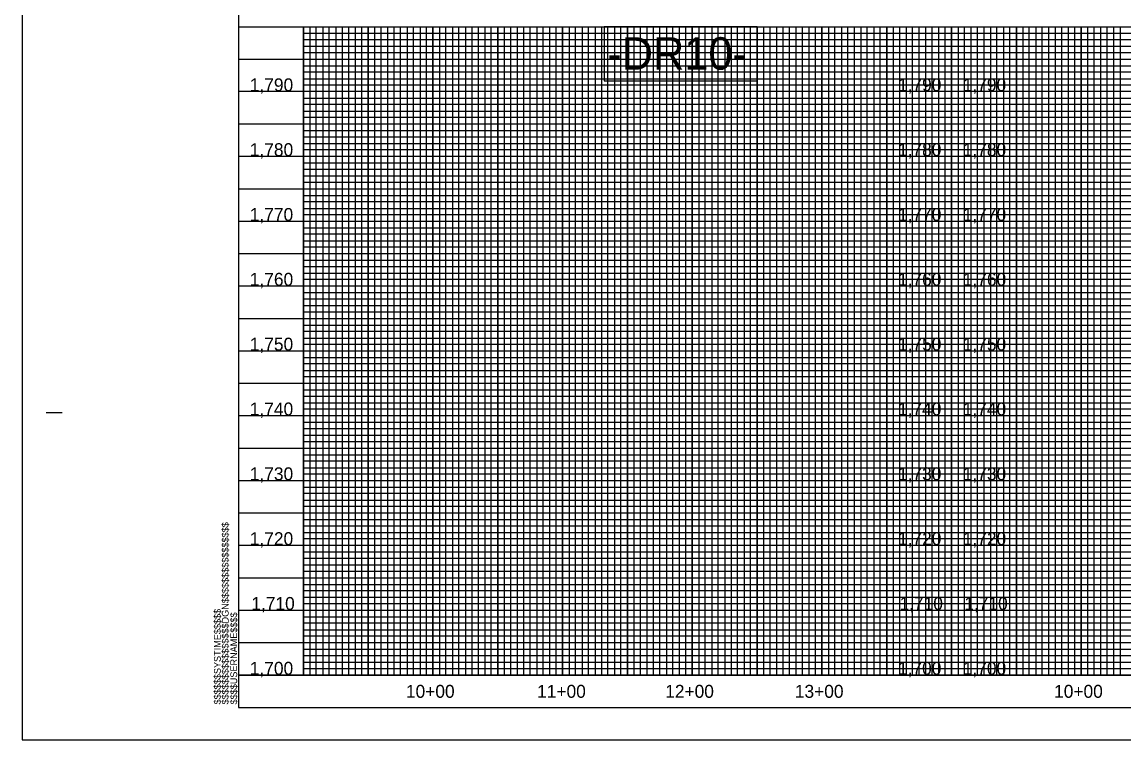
# Model space of a CAD drawing. Extents: x 505602 to 507286, y 483109 to 484209.
# Drawn here: x 505602 to 506452, y 483109 to 483662 of the extents above; entities that cross this region are included whole.
import ezdxf

# ---------------------------------------------------------------- set-up
doc = ezdxf.new("R2010")
doc.units = 0
for name, color, linetype in [('Exist Vertical Profile Vertical Axis Label', 7, 'Continuous'), ('Old_Level_1', 7, 'Continuous'), ('Prop Grid Mask', 7, 'Continuous'), ('Sheet Layout Profile Border Port 2', 7, 'Continuous'), ('Sheet Plot Border Outside CELL', 7, 'Continuous'), ('Sheet Profile CELL', 7, 'Continuous'), ('Sheet Profile Grid Major CELL', 7, 'Continuous'), ('Sheet Profile Grid Middle CELL', 7, 'Continuous'), ('Sheet Profile Grid Minor CELL', 7, 'Continuous')]:
    doc.layers.add(name, color=color, linetype=linetype)

msp = doc.modelspace()

# ---------------------------------------------------------------- linework, layer by layer
at = {"layer": 'Prop Grid Mask'}
msp.add_lwpolyline([(506169.08, 483658.71), (506051.19, 483658.71), (506051.19, 483617), (506169.08, 483617)], close=True, dxfattribs=at)
at = {"layer": 'Sheet Layout Profile Border Port 2'}
for points in [[(505819.08, 483658.71), (506319.08, 483658.71), (506319.08, 483158.71), (505819.08, 483158.71)], [(506319.08, 483658.71), (506719.08, 483658.71), (506719.08, 483158.71), (506319.08, 483158.71)]]:
    msp.add_lwpolyline(points, close=True, dxfattribs=at)
at = {"layer": 'Sheet Plot Border Outside CELL'}
msp.add_lwpolyline([(505602.08, 483108.71), (507286.08, 483108.71), (507286.08, 484208.71), (505602.08, 484208.71)], close=True, dxfattribs=at)
at = {"layer": 'Sheet Profile CELL'}
for p, q in [((505769.08, 483658.71), (507269.08, 483658.71)), ((506319.08, 483158.71), (506319.08, 483658.71)), ((505620.58, 483361.21), (505633.08, 483361.21)), ((507269.08, 483158.71), (505769.08, 483158.71)), ((505769.08, 483133.71), (507269.08, 483133.71)), ((505769.08, 483133.71), (505769.08, 483133.71)), ((505769.08, 483133.71), (505769.08, 483133.71)), ((505769.08, 483133.71), (505769.08, 483133.71)), ((505769.08, 483133.71), (505769.08, 483133.71)), ((505769.08, 483133.71), (505769.08, 483133.71)), ((505769.08, 483133.71), (505769.08, 483133.71)), ((505769.08, 483133.71), (505769.08, 483133.71))]:
    msp.add_line(p, q, dxfattribs=at)
msp.add_lwpolyline([(507269.08, 484183.71), (505769.08, 484183.71), (505769.08, 483133.71), (507269.08, 483133.71)], close=True, dxfattribs=at)
msp.add_lwpolyline([(505806.58, 483133.71), (505806.58, 483133.71)], dxfattribs=at)
at = {"layer": 'Sheet Profile Grid Major CELL'}
for p, q in [((506269.08, 483658.71), (506319.08, 483658.71)), ((506369.08, 483658.71), (506419.08, 483658.71))]:
    msp.add_line(p, q, dxfattribs=at)
for points in [[(505769.08, 483658.71), (505769.08, 483158.71), (505819.08, 483158.71), (505819.08, 483658.71), (505869.08, 483658.71), (505869.08, 483158.71), (505919.08, 483158.71), (505919.08, 483658.71), (505969.08, 483658.71), (505969.08, 483158.71), (506019.08, 483158.71), (506019.08, 483658.71), (506069.08, 483658.71), (506069.08, 483158.71), (506119.08, 483158.71), (506119.08, 483658.71), (506169.08, 483658.71), (506169.08, 483158.71), (506219.08, 483158.71), (506219.08, 483658.71), (506269.08, 483658.71), (506269.08, 483158.71), (506319.08, 483158.71), (506319.08, 483658.71), (506369.08, 483658.71), (506369.08, 483158.71), (506419.08, 483158.71), (506419.08, 483658.71), (506469.08, 483658.71)], [(505819.08, 483658.71), (505819.08, 483158.71), (505869.08, 483158.71), (505869.08, 483658.71), (505919.08, 483658.71), (505919.08, 483158.71), (505969.08, 483158.71), (505969.08, 483658.71), (506019.08, 483658.71), (506019.08, 483158.71), (506069.08, 483158.71), (506069.08, 483658.71), (506119.08, 483658.71), (506119.08, 483158.71), (506169.08, 483158.71), (506169.08, 483658.71), (506219.08, 483658.71), (506219.08, 483158.71), (506269.08, 483158.71), (506269.08, 483658.71), (506319.08, 483658.71), (506319.08, 483158.71), (506369.08, 483158.71), (506369.08, 483658.71), (506419.08, 483658.71), (506419.08, 483158.71), (506469.08, 483158.71)], [(507269.08, 483608.71), (505769.08, 483608.71)], [(507269.08, 483558.71), (505769.08, 483558.71), (505769.08, 483508.71), (507269.08, 483508.71)], [(507269.08, 483458.71), (505769.08, 483458.71), (505769.08, 483408.71), (507269.08, 483408.71)], [(507269.08, 483358.71), (505769.08, 483358.71), (505769.08, 483308.71), (507269.08, 483308.71)], [(507269.08, 483258.71), (505769.08, 483258.71), (505769.08, 483258.71), (505769.08, 483208.71), (507269.08, 483208.71)], [(507269.08, 483158.71), (505769.08, 483158.71)]]:
    msp.add_lwpolyline(points, dxfattribs=at)
at = {"layer": 'Sheet Profile Grid Middle CELL'}
for points in [[(505794.08, 483658.71), (505844.08, 483658.71), (505844.08, 483158.71), (505894.08, 483158.71), (505894.08, 483658.71), (505944.08, 483658.71), (505944.08, 483158.71), (505994.08, 483158.71), (505994.08, 483658.71), (506044.08, 483658.71), (506044.08, 483158.71), (506094.08, 483158.71), (506094.08, 483658.71), (506144.08, 483658.71), (506144.08, 483158.71), (506194.08, 483158.71), (506194.08, 483658.71), (506244.08, 483658.71), (506244.08, 483158.71), (506294.08, 483158.71), (506294.08, 483658.71), (506344.08, 483658.71), (506344.08, 483158.71), (506394.08, 483158.71), (506394.08, 483158.71), (506394.08, 483658.71), (506444.08, 483658.71), (506444.08, 483158.71), (506494.08, 483158.71)], [(505769.08, 483633.71), (507269.08, 483633.71)], [(507269.08, 483583.71), (505769.08, 483583.71), (505769.08, 483533.71), (507269.08, 483533.71)], [(507269.08, 483483.71), (505769.08, 483483.71), (505769.08, 483433.71), (507269.08, 483433.71)], [(507269.08, 483383.71), (505769.08, 483383.71), (505769.08, 483333.71), (507269.08, 483333.71)], [(507269.08, 483283.71), (505769.08, 483283.71), (505769.08, 483233.71), (507269.08, 483233.71)], [(507269.08, 483183.71), (505769.08, 483183.71)]]:
    msp.add_lwpolyline(points, dxfattribs=at)
at = {"layer": 'Sheet Profile Grid Minor CELL'}
for p, q in [((505819.08, 483653.71), (507219.08, 483653.71)), ((507219.08, 483648.71), (505819.08, 483648.71)), ((505819.08, 483643.71), (507219.08, 483643.71)), ((507219.08, 483638.71), (505819.08, 483638.71)), ((505819.08, 483628.71), (507219.08, 483628.71)), ((507219.08, 483623.71), (505819.08, 483623.71)), ((505819.08, 483618.71), (507219.08, 483618.71)), ((507219.08, 483613.71), (505819.08, 483613.71)), ((505819.08, 483603.71), (507219.08, 483603.71)), ((507219.08, 483598.71), (505819.08, 483598.71)), ((505819.08, 483593.71), (507219.08, 483593.71)), ((507219.08, 483588.71), (505819.08, 483588.71)), ((505819.08, 483578.71), (507219.08, 483578.71)), ((507219.08, 483573.71), (505819.08, 483573.71)), ((505819.08, 483568.71), (507219.08, 483568.71)), ((507219.08, 483563.71), (505819.08, 483563.71)), ((505819.08, 483553.71), (507219.08, 483553.71)), ((507219.08, 483548.71), (505819.08, 483548.71)), ((505819.08, 483543.71), (507219.08, 483543.71)), ((507219.08, 483538.71), (505819.08, 483538.71)), ((505819.08, 483528.71), (507219.08, 483528.71)), ((507219.08, 483523.71), (505819.08, 483523.71)), ((505819.08, 483518.71), (507219.08, 483518.71)), ((507219.08, 483513.71), (505819.08, 483513.71)), ((505819.08, 483503.71), (507219.08, 483503.71)), ((507219.08, 483498.71), (505819.08, 483498.71)), ((505819.08, 483493.71), (507219.08, 483493.71)), ((507219.08, 483488.71), (505819.08, 483488.71)), ((505819.08, 483478.71), (507219.08, 483478.71)), ((507219.08, 483473.71), (505819.08, 483473.71)), ((505819.08, 483468.71), (507219.08, 483468.71)), ((507219.08, 483463.71), (505819.08, 483463.86)), ((505819.08, 483453.71), (507219.08, 483453.71)), ((507219.08, 483448.71), (505819.08, 483448.71)), ((505819.08, 483443.71), (507219.08, 483443.71)), ((507219.08, 483438.71), (505819.08, 483438.71)), ((505819.08, 483428.71), (507219.08, 483428.71)), ((507219.08, 483423.71), (505819.08, 483423.71)), ((505819.08, 483418.71), (507219.08, 483418.71)), ((507219.08, 483413.71), (505819.08, 483413.71)), ((505819.08, 483403.71), (507219.08, 483403.71)), ((507219.08, 483398.71), (505819.08, 483398.71)), ((505819.08, 483393.71), (507219.08, 483393.71)), ((507219.08, 483388.71), (505819.08, 483388.71)), ((505819.08, 483378.71), (507219.08, 483378.71)), ((507219.08, 483373.71), (505819.08, 483373.71)), ((505819.08, 483368.71), (507219.08, 483368.71)), ((507219.08, 483363.71), (505819.08, 483363.71)), ((505819.08, 483353.71), (507219.08, 483353.71)), ((507219.08, 483348.71), (505819.08, 483348.71)), ((505819.08, 483343.71), (507219.08, 483343.71)), ((507219.08, 483338.71), (505819.08, 483338.71)), ((505819.08, 483328.71), (507219.08, 483328.71)), ((507219.08, 483323.71), (505819.08, 483323.71)), ((505819.08, 483318.71), (507219.08, 483318.71)), ((507219.08, 483313.71), (505819.08, 483313.71)), ((505819.08, 483303.71), (507219.08, 483303.71)), ((507219.08, 483298.71), (505819.08, 483298.71)), ((505819.08, 483293.71), (507219.08, 483293.71)), ((507219.08, 483288.71), (505819.08, 483288.71)), ((505819.08, 483278.71), (507219.08, 483278.71)), ((507219.08, 483273.71), (505819.08, 483273.71)), ((505819.08, 483268.71), (507219.08, 483268.71)), ((507219.08, 483263.71), (505819.08, 483263.71)), ((505819.08, 483253.71), (507219.08, 483253.71)), ((507219.08, 483248.71), (505819.08, 483248.71)), ((505819.08, 483243.71), (507219.08, 483243.71)), ((507219.08, 483238.71), (505819.08, 483238.71)), ((505819.08, 483228.71), (507219.08, 483228.71)), ((507219.08, 483223.71), (505819.08, 483223.71)), ((505819.08, 483218.71), (507219.08, 483218.71)), ((507219.08, 483213.71), (505819.08, 483213.71)), ((505819.08, 483203.71), (507219.08, 483203.71)), ((507219.08, 483198.71), (505819.08, 483198.71)), ((505819.08, 483193.71), (507219.08, 483193.71)), ((507219.08, 483188.71), (505819.08, 483188.71)), ((505819.08, 483178.71), (507219.08, 483178.71)), ((507219.08, 483173.71), (505819.08, 483173.71)), ((505819.08, 483168.71), (507219.08, 483168.71)), ((505819.08, 483163.71), (507219.08, 483163.71))]:
    msp.add_line(p, q, dxfattribs=at)
for points in [[(505819.08, 483658.71), (505824.08, 483658.71), (505824.08, 483158.71), (505829.08, 483158.71), (505829.08, 483658.71), (505834.08, 483658.71), (505834.08, 483158.71), (505839.08, 483158.71), (505839.08, 483658.71), (505849.08, 483658.71), (505849.08, 483158.71), (505854.08, 483158.71), (505854.08, 483658.71), (505859.08, 483658.71), (505859.08, 483158.71), (505864.08, 483158.71), (505874.08, 483158.71), (505879.08, 483158.71), (505879.08, 483658.71), (505884.08, 483658.71), (505884.08, 483158.71), (505889.08, 483158.71), (505889.08, 483658.71), (505899.08, 483658.71), (505899.08, 483158.71), (505904.08, 483158.71), (505904.08, 483658.71), (505909.08, 483658.71), (505909.08, 483158.71), (505914.08, 483158.71), (505914.08, 483658.71), (505924.08, 483658.71), (505924.08, 483158.71), (505929.08, 483158.71), (505929.08, 483658.71), (505934.08, 483658.71), (505934.08, 483158.71), (505939.08, 483158.71), (505939.08, 483658.71), (505949.08, 483658.71), (505949.08, 483158.71), (505954.08, 483158.71), (505954.08, 483658.71), (505959.08, 483658.71), (505959.08, 483158.71), (505964.08, 483158.71), (505964.08, 483658.71), (505974.08, 483658.71), (505974.08, 483158.71), (505979.08, 483158.71), (505979.08, 483658.71), (505984.08, 483658.71), (505984.08, 483158.71), (505989.08, 483158.71), (505989.08, 483658.71), (505999.08, 483658.71), (505999.08, 483158.71), (506004.08, 483158.71), (506004.08, 483658.71), (506009.08, 483658.71), (506009.08, 483158.71), (506014.08, 483158.71), (506014.08, 483658.71), (506024.08, 483658.71), (506024.08, 483158.71), (506029.08, 483158.71), (506029.08, 483658.71), (506034.08, 483658.71), (506034.08, 483158.71)], [(505864.08, 483158.71), (505864.08, 483658.71), (505874.08, 483658.71), (505874.08, 483158.71)], [(506034.08, 483158.71), (506039.08, 483158.71), (506039.08, 483658.71), (506049.08, 483658.71), (506049.08, 483158.71), (506054.08, 483158.71), (506054.08, 483658.71), (506059.08, 483658.71), (506059.08, 483158.71), (506064.08, 483158.71), (506064.08, 483658.71), (506074.08, 483658.71), (506074.08, 483158.71), (506079.08, 483158.71), (506079.08, 483658.71), (506084.08, 483658.71), (506084.08, 483158.71), (506089.08, 483158.71), (506089.08, 483658.71), (506099.08, 483658.71), (506099.08, 483158.71), (506104.08, 483158.71), (506104.08, 483658.71), (506109.08, 483658.71), (506109.08, 483158.71), (506114.08, 483158.71), (506114.08, 483658.71), (506124.08, 483658.71), (506124.08, 483158.71), (506129.08, 483158.71), (506129.08, 483658.71), (506134.08, 483658.71), (506134.08, 483158.71), (506139.08, 483158.71), (506139.08, 483658.71), (506149.08, 483658.71), (506149.08, 483158.71), (506154.08, 483158.71), (506154.08, 483658.71), (506159.08, 483658.71), (506159.08, 483158.71), (506164.08, 483158.71), (506164.08, 483658.71), (506174.08, 483658.71), (506174.08, 483158.71), (506179.08, 483158.71), (506179.08, 483658.71), (506184.08, 483658.71), (506184.08, 483158.71), (506189.08, 483158.71), (506189.08, 483658.71), (506199.08, 483658.71), (506199.08, 483158.71), (506204.08, 483158.71), (506204.08, 483658.71), (506209.08, 483658.71), (506209.08, 483158.71), (506214.08, 483158.71), (506214.08, 483658.71), (506224.08, 483658.71), (506224.08, 483158.71), (506229.08, 483158.71), (506229.08, 483658.71), (506234.08, 483658.71), (506234.08, 483158.71), (506239.08, 483158.71), (506239.08, 483658.71), (506249.08, 483658.71), (506249.08, 483158.71), (506254.08, 483158.71), (506254.08, 483658.71), (506259.08, 483658.71), (506259.08, 483158.71), (506264.08, 483158.71), (506264.08, 483658.71), (506274.08, 483658.71), (506274.08, 483158.71), (506279.08, 483158.71), (506279.08, 483658.71), (506284.08, 483658.71), (506284.08, 483158.71), (506289.08, 483158.71), (506289.08, 483658.71), (506299.08, 483658.71), (506299.08, 483158.71), (506304.08, 483158.71), (506304.08, 483658.71), (506309.08, 483658.71), (506309.08, 483158.71), (506314.08, 483158.71), (506314.08, 483658.71), (506324.08, 483658.71), (506324.08, 483158.71), (506329.08, 483158.71), (506329.08, 483658.71), (506334.08, 483658.71), (506334.08, 483158.71), (506339.08, 483158.71), (506339.08, 483658.71), (506349.08, 483658.71)], [(506349.08, 483658.71), (506349.08, 483158.71), (506354.08, 483158.71), (506354.08, 483658.71), (506359.08, 483658.71), (506359.08, 483158.71), (506364.08, 483158.71), (506364.08, 483658.71), (506374.08, 483658.71), (506374.08, 483158.71), (506379.08, 483158.71), (506379.08, 483658.71), (506384.08, 483658.71), (506384.08, 483158.71), (506389.08, 483158.71), (506389.08, 483658.71), (506399.08, 483658.71), (506399.08, 483158.71), (506404.08, 483158.71), (506404.08, 483658.71), (506409.08, 483658.71), (506409.08, 483158.71), (506414.08, 483158.71), (506414.08, 483658.71), (506424.08, 483658.71), (506424.08, 483158.71), (506429.08, 483158.71), (506429.08, 483658.71), (506434.08, 483658.71), (506434.08, 483158.71), (506439.08, 483158.71), (506439.08, 483658.71), (506449.08, 483658.71), (506449.08, 483158.71), (506454.08, 483158.71)]]:
    msp.add_lwpolyline(points, dxfattribs=at)

# ---------------------------------------------------------------- texts
at = {"layer": 'Exist Vertical Profile Vertical Axis Label'}
for s, p in [('1,790', (505777.78, 483608.96)), ('1,790', (506277.78, 483608.96)), ('1,790', (506327.78, 483608.96)), ('1,780', (505777.78, 483558.96)), ('1,780', (506277.78, 483558.96)), ('1,780', (506327.78, 483558.96)), ('1,770', (505777.78, 483508.96)), ('1,770', (506277.78, 483508.96)), ('1,770', (506327.78, 483508.96)), ('1,760', (505777.78, 483458.96)), ('1,760', (506277.78, 483458.96)), ('1,760', (506327.78, 483458.96)), ('1,750', (505777.78, 483408.96)), ('1,750', (506277.78, 483408.96)), ('1,750', (506327.78, 483408.96)), ('1,740', (505777.78, 483358.96)), ('1,740', (506277.78, 483358.96)), ('1,740', (506327.78, 483358.96)), ('1,730', (505777.78, 483308.96)), ('1,730', (506277.78, 483308.96)), ('1,730', (506327.78, 483308.96)), ('1,720', (505777.78, 483258.96)), ('1,720', (506277.78, 483258.96)), ('1,720', (506327.78, 483258.96)), ('1,710', (505778.97, 483208.96)), ('1,710', (506278.97, 483208.96)), ('1,710', (506328.97, 483208.96)), ('1,700', (505777.78, 483158.96)), ('1,700', (506277.78, 483158.96)), ('1,700', (506327.78, 483158.96)), ('10+00', (505898.21, 483141.21)), ('11+00', (505999.41, 483141.21)), ('12+00', (506098.21, 483141.21)), ('13+00', (506198.21, 483141.21)), ('10+00', (506398.21, 483141.21))]:
    msp.add_text(s, height=10, dxfattribs=at).set_placement(p)
at = {"layer": 'Old_Level_1'}
msp.add_text('-DR10-', height=25, dxfattribs=at).set_placement((506053.53, 483625.68))
at = {"layer": 'Sheet Profile CELL'}
for s, p in [('$$$$$$$$$$$$$$$$DGN$$$$$$$$$$$$$$$$', (505761.44, 483136.09)), ('$$$$$$SYSTIME$$$$$', (505755.39, 483136.09)), ('$$$$USERNAME$$$$', (505768.02, 483136.1))]:
    msp.add_text(s, height=5.25, rotation=90, dxfattribs=at).set_placement(p)

doc.saveas('drawing.dxf')
